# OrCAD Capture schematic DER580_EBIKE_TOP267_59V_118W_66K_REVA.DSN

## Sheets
1 PAGE2: size B
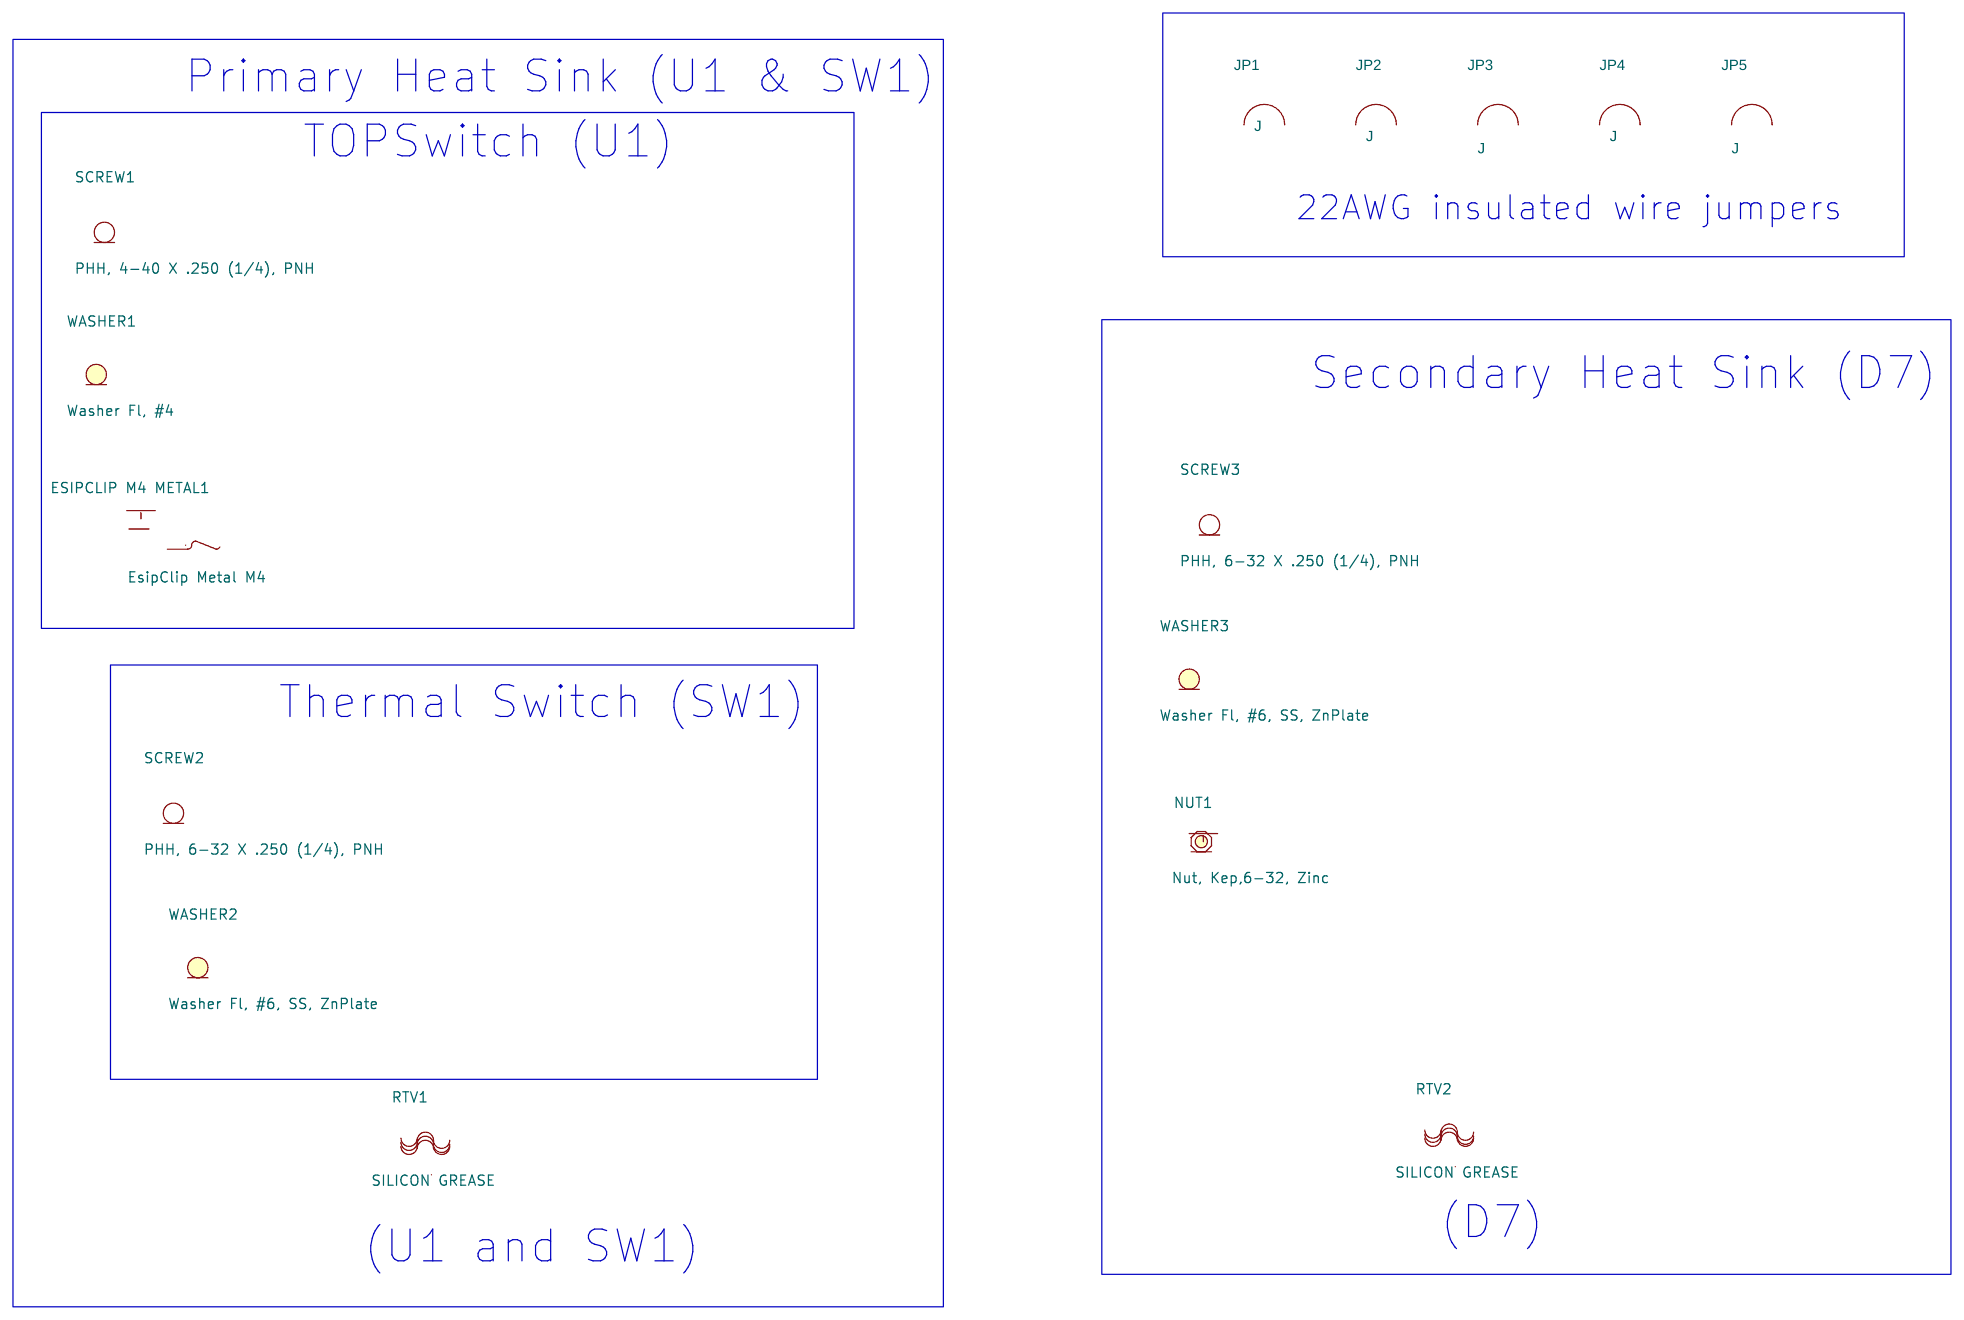
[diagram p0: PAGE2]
2 PAGE1: size C
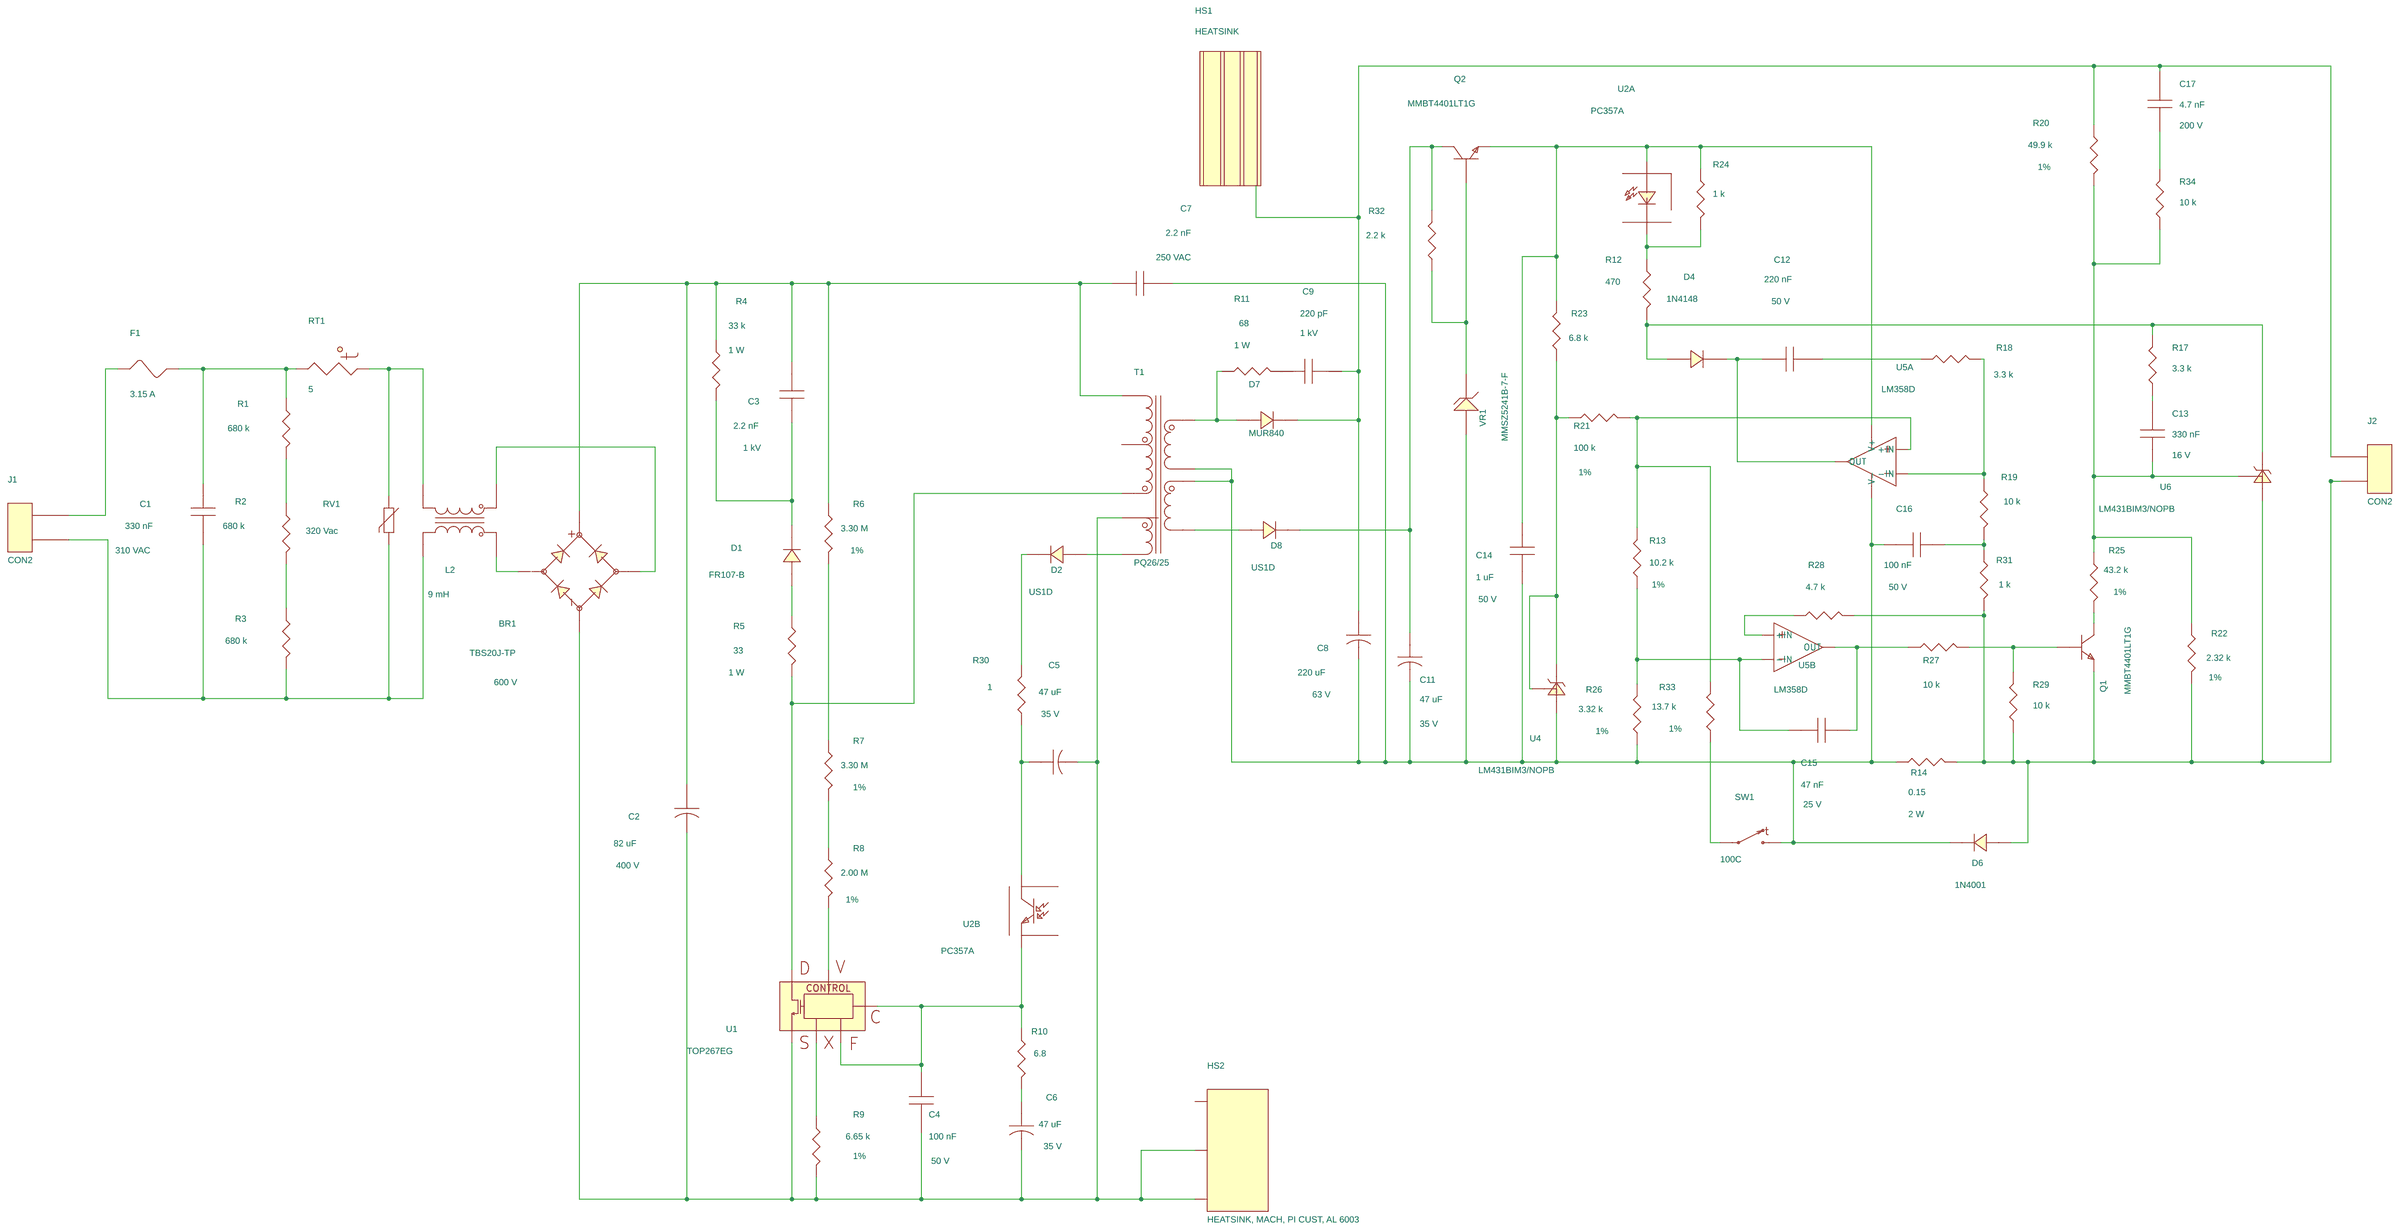
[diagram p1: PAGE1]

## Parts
sheet PAGE1
BR1  TBS20J-TP  [pismd_4-TBS]
C1  330 nF  [pinpxcaprad710x315590046]
C2  82 uF  [pipolcapclyd710ls300040]
C3  2.2 nF  [pinpcaprad350x100200030]
C4  100 nF  [pismc0603]
C5  47 uF  [pipolcapclyd200ls80030]
C6  47 uF  [pipolcapclyd200ls80030]
C7  2.2 nF  [pinpycaprad540x290ls400040]
C8  220 uF  [pipolcapcyld400ls200040]
C9  220 pF  [pinpcaprad250x100200030]
C11  47 uF  [pipolcapclyd200ls80030]
C12  220 nF  [pismc0603]
C13  330 nF  [pismc0603]
C14  1 uF  [pismc0805]
C15  47 nF  [pismc0603]
C16  100 nF  [pismc0805]
C17  4.7 nF  [pismc0805]
D1  FR107-B  [pidv200x110x040do41]
D2  US1D  [pismdsma]
D4  1N4148  [pidv200x080x030do35]
D6  1N4001  [pidv200x110x040do41]
D7  MUR840  [pidvt0220acreva]
D8  US1D  [pismdsma]
F1  3.15 A  [pi_rst_microfuse]
HS1  HEATSINK  [pi_hs_TO220_vert]
HS2  HEATSINK, MACH, PI CUST, AL 6003  [pi_hs_der580_2]
J1  CON2  [pi_hdr_2pin_ls156_lck]
J2  CON2  [pi_hdr_2pin]
L2  9 mH  [piind4p827x433ls315x354031]
Q1  MMBT4401LT1G  [pismsot23123_1]
Q2  MMBT4401LT1G  [pismsot23123_1]
R1  680 k  [pismr1206]
R2  680 k  [pismr1206]
R3  680 k  [pismr1206]
R4  33 k  [pi1wresd200ls725d040]
R5  33  [pi1wresd200ls725d040]
R6  3.30 M  [pismr1206]
R7  3.30 M  [pismr1206]
R8  2.00 M  [pismr1206]
R9  6.65 k  [pismr1206]
R10  6.8  [pismr0603]
R11  68  [pi1wvresd200ls200d040]
R12  470  [pismr0805]
R13  10.2 k  [pismr0805]
R14  0.15  [pi2wresd200ls725d040]
R17  3.3 k  [pismr0603]
R18  3.3 k  [pismr0805]
R19  10 k  [pismr0805]
R20  49.9 k  [pismr0805]
R21  100 k  [pismr0805]
R22  2.32 k  [pismr0603]
R23  6.8 k  [pismr0805]
R24  1 k  [pismr0805]
R25  43.2 k  [pismr0603]
R26  3.32 k  [pismr0805]
R27  10 k  [pismr0603]
R28  4.7 k  [pismr0603]
R29  10 k  [pismr0603]
R30  1  [pismr0805]
R31  1 k  [pismr0805]
R32  2.2 k  [pismr0603]
R33  13.7 k  [pi14wvresd100ls100d030]
R34  10 k  [pismr0603]
RT1  5  [pirad400x175ls250040]
RV1  320 Vac  [pi_disc_335x240ls200d040]
SW1  100C  [pi_PB_SPST_TP11]
T1  PQ26/25  [PI_DER-569_XFRMR]
U1  TOP267EG  [piicesip76th]
U2  PC357A  [pi_4_smd]  (sections A,B)
U4  LM431BIM3/NOPB  [pismsot23123]
U5  LM358D  [pismso8]  (sections A,B)
U6  LM431BIM3/NOPB  [pismsot23123]
VR1  MMSZ5241B-7-F  [pi_sm_sod-123_12]
sheet PAGE2
ESIPCLIP M4 METAL1  EsipClip Metal M4
JP1  J  [pi_jumper200]
JP2  J  [pi_jumper300]
JP3  J  [pi_jumper900]
JP4  J  [pi_jumper400]
JP5  J  [pi_jumper700]
NUT1  Nut, Kep,6-32, Zinc
RTV1  SILICON GREASE
RTV2  SILICON GREASE
SCREW1  PHH, 4-40 X .250 (1/4), PNH
SCREW2  PHH, 6-32 X .250 (1/4), PNH
SCREW3  PHH, 6-32 X .250 (1/4), PNH
WASHER1  Washer Fl, #4
WASHER2  Washer Fl, #6, SS, ZnPlate
WASHER3  Washer Fl, #6, SS, ZnPlate

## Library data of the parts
BR1 = DIODE_BRIDGE_+-~~: Disp_Voltage: 600 V; Part Number: 15-01174-00
C1 = CAP_NP: Disp_Voltage: 310 VAC; Part Number: 20-08604-00; Voltage: 310 VAC
C2 = CAP_POL: ALT_SYMBOLS: pi_cap_cly_d710_ls300_040_1035h; Disp_Voltage: 400 V; FPLIST: pipolcapclyd710ls300040,pi_cap_cly_d710_ls300_040_1035h; Part Number: 20-00823-00; Voltage: 400 V
C3 = CAP_NP: Disp_Voltage: 1 kV; Part Number: 20-00357-00; Voltage: 1 kV
C4 = CAP_NP: Disp_Voltage: 50 V; Part Number: 20-00936-00; Voltage: 50 V
C5 C6 C11 = CAP_POL: ALT_SYMBOLS: pipolcapclyd200ls80030l460h; Disp_Voltage: 35 V; FPLIST: pipolcapclyd200ls80030,pipolcapclyd200ls80030l460h; Part Number: 20-00726-00; Voltage: 35 V
C7 = CAP_NP: ALT_SYMBOLS: pinpycaprad540x290ls400040h; Disp_Voltage: 250 VAC; FPLIST: pinpycaprad540x290ls400040,pinpycaprad540x290ls400040h; Part Number: 20-00376-00; Voltage: 250 VAC
C8 = CAP_POL: Disp_Voltage: 63 V; Part Number: 20-00981-00; Voltage: 63 V
C9 = CAP_NP: Disp_Voltage: 1 kV; Part Number: 20-00354-00; Voltage: 1 kV
C12 = CAP_NP: Disp_Voltage: 50 V; Part Number: 20-08624-00; Voltage: 50 V
C13 = CAP_NP: Disp_Voltage: 16 V; Part Number: 20-08755-00; Voltage: 16 V
C14 = CAP_NP: Disp_Voltage: 50 V; Part Number: 20-01022-00; Voltage: 50 V
C15 = CAP_NP: Disp_Voltage: 25 V; Part Number: 20-08756-00; Voltage: 25 V
C16 = CAP_NP: Disp_Voltage: 50 V; Part Number: 20-00904-00; Voltage: 50 V
C17 = CAP_NP: Disp_Voltage: 200 V; Part Number: 20-08570-00; Voltage: 200 V
D1 = DIODE: ALT_SYMBOLS: pidax475x125040do41,pidv200x110x040do41wbead,pidax390x125040do41; FPLIST: pidv200x110x040do41,pidax475x125040do41,pidv200x110x040do41wbead,pidax390x125040do41; Part Number: 15-00956-00
D2 D8 = DIODE: Part Number: 15-00492-00
D4 = DIODE: ALT_SYMBOLS: pidax375x070030do35,pidv100x080x030do35; FPLIST: pidv200x080x030do35,pidax375x070030do35,pidv100x080x030do35; Part Number: 15-00083-00
D6 = DIODE: ALT_SYMBOLS: pidax475x125040do41,pidv200x110x040do41wbead,pidax390x125040do41; FPLIST: pidv200x110x040do41,pidax475x125040do41,pidv200x110x040do41wbead,pidax390x125040do41; Part Number: 15-01169-00
D7 = DIODE: Part Number: 15-00124-00
F1 = FUSE: ALT_SYMBOLS: pirstmicrofusehoz; FPLIST: pi_rst_microfuse,pirstmicrofusehoz; Part Number: 40-00020-00
HS1 = HS-PI_CUSTOM2: Part Number: 60-00093-00
HS2 = HS-PI_CUSTOM_3P: Part Number: 61-00214-01
J1 = CON2: Part Number: 35-00273-00
J2 = CON2: Part Number: 35-00001-00
L2 = INDUCTOR_4P_revG: Part Number: 30-00402-00
Q1 Q2 = NPN_BEC: Part Number: 55-00059-00
R1-R3 = R: Part Number: 05-01420-00
R4 = R: ALT_SYMBOLS: pi1wvresd120ls200d040,pi1wvresd120ls300d040,pi1wvresd200ls200d040,pi1wvresd200ls300d040,pi1wvresd200ls350d040; Disp_Power: 1 W; FPLIST: pi1wresd200ls725d040,pi1wvresd120ls200d040,pi1wvresd120ls300d040,pi1wvresd200ls200d040,pi1wvresd200ls300d040,pi1wvresd200ls350d040; Part Number: 05-02888-00
R5 = R: ALT_SYMBOLS: pi1wvresd120ls200d040,pi1wvresd120ls300d040,pi1wvresd200ls200d040,pi1wvresd200ls300d040,pi1wvresd200ls350d040; Disp_Power: 1 W; FPLIST: pi1wresd200ls725d040,pi1wvresd120ls200d040,pi1wvresd120ls300d040,pi1wvresd200ls200d040,pi1wvresd200ls300d040,pi1wvresd200ls350d040; Part Number: 05-02816-00
R6 R7 = R: Disp_Tol: 1%; Part Number: 05-05359-00
R8 = R: Disp_Tol: 1%; Part Number: 05-03156-00
R9 = R: Disp_Tol: 1%; Part Number: 05-00272-00
R10 = R: Part Number: 05-01636-00
R11 = R: ALT_SYMBOLS: pi1wvresd120ls200d040,pi1wvresd120ls300d040,pi1wvresd200ls200d040,pi1wvresd200ls300d040,pi1wvresd200ls350d040; Disp_Power: 1 W; FPLIST: pi1wresd200ls725d040,pi1wvresd120ls200d040,pi1wvresd120ls300d040,pi1wvresd200ls200d040,pi1wvresd200ls300d040,pi1wvresd200ls350d040; Part Number: 05-02824-00
R12 = R: Part Number: 05-01511-00
R13 = R: Disp_Tol: 1%; Part Number: 05-00685-00
R14 = R: Disp_Power: 2 W; FPLIST: pi2wresd200ls725d040,pi2wresd200ls900d040,pi2wvresd200ls300d040,pi2wvresd200ls400d040; Part Number: 05-03407-00
R17 = R: Part Number: 05-01700-00
R18 = R: Part Number: 05-01531-00
R19 = R: Part Number: 05-01543-00
R20 = R: Disp_Tol: 1%; Part Number: 05-00751-00
R21 = R: Disp_Tol: 1%; Part Number: 05-00780-00
R22 = R: Disp_Tol: 1%; Part Number: 05-01113-00
R23 = R: Part Number: 05-01539-00
R24 R31 = R: Part Number: 05-01519-00
R25 = R: Disp_Tol: 1%; Part Number: 05-03245-00
R26 = R: Disp_Tol: 1%; Part Number: 05-03358-00
R27 R29 R34 = R: Part Number: 05-01712-00
R28 = R: Part Number: 05-01704-00
R30 = R: Part Number: 05-01447-00
R32 = R: Part Number: 05-01696-00
R33 = R: ALT_SYMBOLS: pi14wvresd100ls200d030,pi14wresd100ls400d030,pi14wresd100ls500d030; Disp_Tol: 1%; FPLIST: pi14wvresd100ls100d030,pi14wvresd100ls200d030,pi14wresd100ls400d030,pi14wresd100ls500d030; Part Number: 05-02085-00
RT1 = THERMISTOR: Part Number: 90-00014-00
RV1 = VARISTOR: Part Number: 85-00020-00
SW1 = SW_Thermal_NC: Part Number: 66-00207-00
T1 = DER-569_XFRMR: Part Number: 25-01097-00
U1 = TOP26X_EG: Part Number: 10-00374-00
U2 = OPTO_A_B: Part Number: 53-00003-00
U4 U6 = TL431_SOT-23_CAR: Part Number: 45-00232-00
U5 = LM358: Part Number: 45-00050-00
VR1 = DIODE_ZENER: Part Number: 15-01089-00
ESIPCLIP M4 METAL1 = EsipClip_Metal_M4: Part Number: 60-00042-00
JP1 = JUMPER_1: Part Number: 65-00041-00
JP2 = JUMPER_1: Part Number: 65-00042-00
JP3 = JUMPER_1: Part Number: 65-00048-00
JP4 = JUMPER_1: Part Number: 65-00043-00
JP5 = JUMPER_1: Part Number: 65-00046-00
NUT1 = NUT_HEX_4-40: Part Number: 75-00069-00
RTV1 RTV2 = RTV: Part Number: 66-00084-00
SCREW1 = SCR_4-40: Part Number: 75-00001-00
SCREW2 SCREW3 = SCR_6-32: Part Number: 75-00007-00
WASHER1 = WASH_FLAT_4: Part Number: 75-00032-00
WASHER2 WASHER3 = WASH_FLAT_6: Part Number: 75-00167-00

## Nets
N00906: C8.1 C9.2 C17.2 D7.1 HS1.1 J2.1 R20.1
N01215: C7.2 C8.2 C11.2 C14.2 C16.2 D6.1 R14.1 R26.1 SW1.2 T1.8 T1.9 U4.2(A) U5.4(V-) VR1.2
N01329: BR1.1 C2.1 C3.2 C7.1 R4.1 R6.1 T1.1
N01364: BR1.2 C2.2 C4.2 C5.2 C6.2 HS2.1 HS2.2 R9.2 T1.4 U1.5(S)
N01421: BR1.3 L2.1
N01764: L2.3 RT1.2 RV1.1
N01812: C1.2 J1.1 L2.4 R3.2 RV1.2
N01821: R2.2 R3.1
N01839: R1.2 R2.1
N02417: C1.1 F1.2 R1.1 RT1.1
N03024: R9.1 U1.2(X)
N03093: C4.1 R10.1 U1.3(C) U1.4(F) U2.3(E)
N03111: C6.1 R10.2
N03136: R8.2 U1.1(V)
N03143: R7.2 R8.1
N03168: R6.2 R7.1
N07742: D2.1 R30.2
N07860: C5.1 R30.1 U2.4(C)
N08806: D6.2 J2.2 Q1.2(EMITTER) R14.2 R22.2 R28.2 R29.1 R31.2 U6.2(A)
N09675: R18.2 R19.1 U5.2(-IN)
N09924: C13.1 R20.2 R22.1 R25.1 R34.1 U6.3(VREF)
N16567: C3.1 D1.1 R4.2
N18059: F1.1 J1.2
N22833: R5.2 T1.3 U1.7(D)
N24164: R12.1 R24.2 U2.2(C)
N24263: C12.2 R18.1
N24295: C12.1 D4.1 U5.1(OUT)
N24455: D4.2 R12.2 R17.2 U6.1(C)
N26109: R21.1 R23.1 U4.1(C) U4.3(VREF)
N27634: R13.2 R21.2 R33.2 U5.3(+IN)
N29605: C14.1 Q2.2(EMITTER) R23.2 R24.1 U2.1(A) U5.8(V+)
N48309: D1.2 R5.1
N56239: BR1.4 L2.2
N77874: D7.2 R11.1 T1.11
N81445: C11.1 D8.1 Q2.3(COLLECTOR) R32.2
N82880: C15.2 R13.1 R26.2 U5.6(-IN)
N87772: C13.2 R17.1
N89028: C15.1 R27.1 U5.7(OUT)
N89032: Q1.1(BASE) R27.2 R29.2
N94097: C9.1 R11.2
N99851: R28.1 U5.5(+IN)
N104378: D8.2 T1.7
N110778: D2.2 T1.5
N118670: Q1.3(COLLECTOR) R25.2
N119358: C16.1 R19.2 R31.1
N133377: Q2.1(BASE) R32.1 VR1.1
N137748: R33.1 SW1.1
N145658: C17.1 R34.2

Not connected (* = marked no-connect by the designer): HS1 2; HS2 3; JP1 1 2; JP2 1 2; JP3 1 2; JP4 1 2; JP5 1 2; T1 2

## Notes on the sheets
sheet 1
- Primary Heat Sink (U1 & SW1)
- TOPSwitch (U1)
- 22AWG insulated wire jumpers
- Secondary Heat Sink (D7)
- Thermal Switch (SW1)
- (D7)
- (U1 and SW1)
